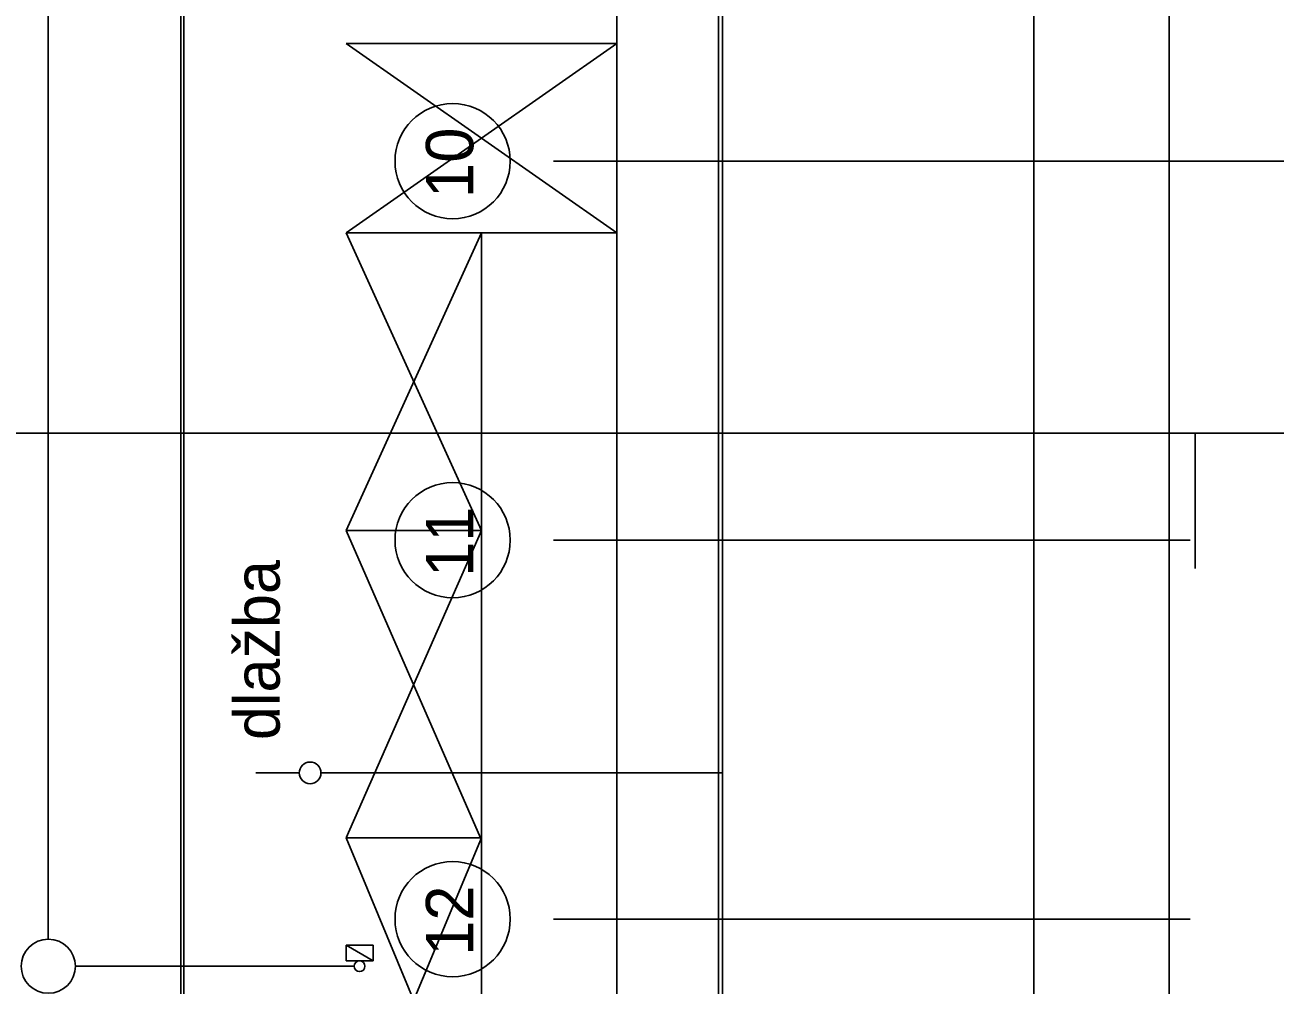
# Model space of a CAD drawing. Extents: x -264205 to -263659, y -1242401 to -1241986.
# Drawn here: x -263927.02 to -263903.94, y -1242155.1 to -1242137.37 of the extents above; entities that cross this region are included whole.
import ezdxf

# ---------------------------------------------------------------- set-up
doc = ezdxf.new("R2010")
doc.units = 0
for name, color, linetype in [('HESCON_OSI_STAVBY_KFA', 7, 'Continuous'), ('POPIS_2-3', 7, 'Continuous'), ('PROJEKT_OBRUBNIKY_KOMUNIKACIE', 7, 'Continuous'), ('PROJEKT_TDZ_VODOROVNE', 7, 'Continuous'), ('RAM_NA_TLAC_2-1_1-250', 7, 'Continuous'), ('RAM_NA_TLAC_2-3_1-250', 7, 'Continuous'), ('SITUACIA_DSP_2D', 7, 'Continuous')]:
    doc.layers.add(name, color=color, linetype=linetype)

msp = doc.modelspace()

# ---------------------------------------------------------------- linework, layer by layer
at = {"layer": 'HESCON_OSI_STAVBY_KFA'}
for p, q in [((-263908.393, -1242083.237), (-263908.393, -1242246.707)), ((-263917.265, -1242139.882), (-263905.505, -1242139.882)), ((-263917.265, -1242139.882), (-263905.505, -1242139.882)), ((-263792.653, -1242139.882), (-263909.343, -1242139.882)), ((-263917.265, -1242146.882), (-263905.505, -1242146.882)), ((-263917.265, -1242146.882), (-263905.505, -1242146.882)), ((-263917.265, -1242153.882), (-263905.505, -1242153.882)), ((-263917.265, -1242153.882), (-263905.505, -1242153.882))]:
    msp.add_line(p, q, dxfattribs=at)
for centre in [(-263919.125, -1242139.882), (-263919.125, -1242146.882), (-263919.125, -1242153.882)]:
    msp.add_circle(centre, 1.064, dxfattribs=at)
at = {"layer": 'PROJEKT_OBRUBNIKY_KOMUNIKACIE'}
msp.add_lwpolyline([(-263794.893, -1242227.382), (-263808.968, -1242241.457), (-263894.968, -1242241.457), (-263909.043, -1242227.382), (-263909.043, -1242196.333), (-263914.143, -1242196.333), (-263914.143, -1242132.433), (-263909.043, -1242132.433), (-263909.043, -1242101.382), (-263894.968, -1242087.307), (-263808.968, -1242087.307), (-263794.893, -1242101.382), (-263794.893, -1242227.382)], dxfattribs=at)
at = {"layer": 'PROJEKT_TDZ_VODOROVNE'}
for p, q in [((-263924.088, -1242241.458), (-263924.093, -1242087.307)), ((-263916.093, -1242087.308), (-263916.093, -1242141.207)), ((-263921.093, -1242137.707), (-263916.093, -1242137.707)), ((-263921.093, -1242137.707), (-263916.093, -1242141.207)), ((-263921.093, -1242141.207), (-263916.093, -1242137.707)), ((-263921.093, -1242141.207), (-263916.093, -1242141.207)), ((-263921.093, -1242141.207), (-263918.593, -1242146.702)), ((-263921.093, -1242146.702), (-263918.593, -1242141.207)), ((-263918.593, -1242141.207), (-263918.593, -1242187.557)), ((-263921.093, -1242146.702), (-263918.593, -1242146.702)), ((-263921.093, -1242146.702), (-263918.611, -1242152.382)), ((-263921.093, -1242152.382), (-263918.593, -1242146.702)), ((-263921.093, -1242152.382), (-263918.593, -1242152.382)), ((-263921.093, -1242152.382), (-263918.593, -1242158.382)), ((-263921.093, -1242158.382), (-263918.593, -1242152.382))]:
    msp.add_line(p, q, dxfattribs=at)
at = {"layer": 'RAM_NA_TLAC_2-1_1-250'}
msp.add_line((-263905.413, -1242144.907), (-263905.413, -1242147.407), dxfattribs=at)
msp.add_lwpolyline([(-264147.913, -1242144.907), (-263857.913, -1242144.907), (-263857.913, -1242219.157), (-264147.913, -1242219.157)], close=True, dxfattribs=at)
at = {"layer": 'RAM_NA_TLAC_2-3_1-250'}
msp.add_lwpolyline([(-263980.139, -1242275.511), (-263980.139, -1241985.511), (-263905.889, -1241985.511), (-263905.889, -1242275.511)], close=True, dxfattribs=at)
at = {"layer": 'SITUACIA_DSP_2D'}
for p, q in [((-263924.143, -1242082.64), (-263924.143, -1242185.14)), ((-263926.593, -1242107.902), (-263926.593, -1242154.252)), ((-263926.593, -1242107.902), (-263926.593, -1242154.252)), ((-263916.093, -1242118.282), (-263916.093, -1242175.482)), ((-263914.218, -1242196.332), (-263914.218, -1242132.432)), ((-263914.143, -1242196.333), (-263914.143, -1242132.433)), ((-263921.957, -1242151.182), (-263922.757, -1242151.182)), ((-263917.093, -1242151.182), (-263921.557, -1242151.182)), ((-263914.143, -1242151.182), (-263917.093, -1242151.182)), ((-263921.093, -1242154.652), (-263921.093, -1242154.362)), ((-263921.093, -1242154.362), (-263920.593, -1242154.362)), ((-263920.593, -1242154.652), (-263921.093, -1242154.362)), ((-263920.593, -1242154.652), (-263921.093, -1242154.362)), ((-263921.093, -1242154.362), (-263921.093, -1242154.652)), ((-263920.593, -1242154.362), (-263920.593, -1242154.652)), ((-263920.944, -1242154.752), (-263926.093, -1242154.752)), ((-263920.593, -1242154.652), (-263921.093, -1242154.652)), ((-263921.093, -1242154.652), (-263920.593, -1242154.652))]:
    msp.add_line(p, q, dxfattribs=at)
for centre, radius in [((-263921.757, -1242151.182), 0.2), ((-263926.593, -1242154.752), 0.5), ((-263920.844, -1242154.752), 0.1)]:
    msp.add_circle(centre, radius, dxfattribs=at)

# ---------------------------------------------------------------- texts
at = {"layer": 'HESCON_OSI_STAVBY_KFA'}
for s, p in [('10', (-263918.744, -1242140.562)), ('11', (-263918.744, -1242147.562)), ('12', (-263918.744, -1242154.562))]:
    msp.add_text(s, height=0.875, rotation=90, dxfattribs=at).set_placement(p)
at = {"layer": 'POPIS_2-3'}
msp.add_text('dlažba', height=0.8438, rotation=90, dxfattribs=at).set_placement((-263922.318, -1242150.575))

doc.saveas('drawing.dxf')
